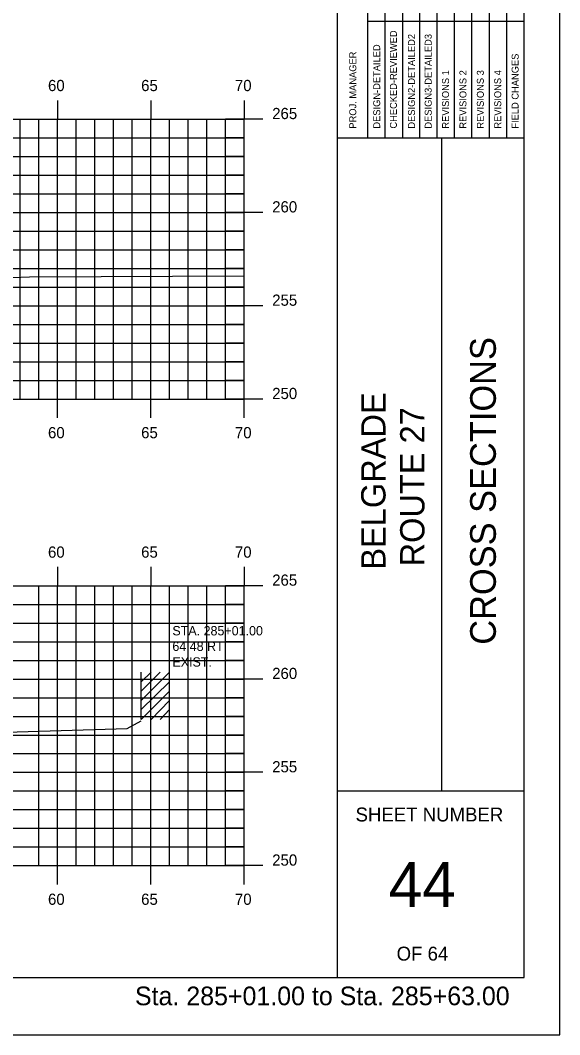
# Model space of a CAD drawing. Extents: x 856680 to 856850, y 366268 to 366378.
# Drawn here: x 856821.1 to 856850, y 366268.2 to 366322.5 of the extents above; entities that cross this region are included whole.
import ezdxf

# ---------------------------------------------------------------- set-up
doc = ezdxf.new("R2010")
doc.units = 0
for name, color, linetype in [('BORDER', 7, 'Continuous'), ('D_Text_Monospaced', 7, 'Continuous'), ('H_V ANNOTATION', 7, 'Continuous'), ('HIGHWAY_TITLE', 7, 'Continuous'), ('MAJOR', 7, 'Continuous'), ('MINOR', 7, 'Continuous'), ('PLOT BOUNDARY', 7, 'Continuous'), ('S_Buildings', 7, 'Continuous'), ('S_Roadway_Centerline', 7, 'Continuous')]:
    doc.layers.add(name, color=color, linetype=linetype)

msp = doc.modelspace()

# ---------------------------------------------------------------- linework, layer by layer
at = {"layer": 'BORDER'}
for p, q in [((856838.116, 366271.236), (856838.116, 366376.239)), ((856848.116, 366271.236), (856848.116, 366376.236)), ((856838.116, 366316.239), (856848.116, 366316.239)), ((856843.707, 366281.239), (856843.707, 366316.239)), ((856838.116, 366281.239), (856848.116, 366281.239)), ((856688.116, 366271.236), (856848.116, 366271.236))]:
    msp.add_line(p, q, dxfattribs=at)
for points in [[(856840.664, 366316.242), (856840.664, 366333.739)], [(856841.596, 366333.739), (856841.596, 366316.242)], [(856842.527, 366316.242), (856842.527, 366333.739)], [(856843.459, 366316.242), (856843.459, 366333.739)], [(856844.391, 366316.242), (856844.391, 366333.739)], [(856845.322, 366316.242), (856845.322, 366333.739)], [(856846.254, 366316.242), (856846.254, 366333.739)], [(856847.186, 366316.242), (856847.186, 366333.739)], [(856839.732, 366316.242), (856839.732, 366333.033)], [(856839.731, 366322.489), (856848.116, 366322.489)]]:
    msp.add_lwpolyline(points, dxfattribs=at)
at = {"layer": 'MAJOR'}
for p, q in [((856823.116, 366318.238), (856823.116, 366317.236)), ((856828.116, 366318.238), (856828.116, 366317.236)), ((856833.116, 366318.238), (856833.116, 366317.236)), ((856693.116, 366317.236), (856833.116, 366317.236)), ((856693.116, 366317.236), (856833.116, 366317.236)), ((856823.116, 366302.236), (856823.116, 366317.236)), ((856828.116, 366302.236), (856828.116, 366317.236)), ((856834.118, 366317.236), (856832.114, 366317.236)), ((856833.116, 366302.236), (856833.116, 366317.236)), ((856833.116, 366302.236), (856833.116, 366317.236)), ((856693.116, 366312.236), (856833.116, 366312.236)), ((856834.118, 366312.236), (856832.114, 366312.236)), ((856693.116, 366307.236), (856833.116, 366307.236)), ((856834.118, 366307.236), (856832.114, 366307.236)), ((856693.116, 366302.236), (856833.116, 366302.236)), ((856693.116, 366302.236), (856833.116, 366302.236)), ((856823.116, 366301.234), (856823.116, 366302.236)), ((856828.116, 366301.234), (856828.116, 366302.236)), ((856834.118, 366302.236), (856832.114, 366302.236)), ((856833.116, 366301.234), (856833.116, 366302.236)), ((856823.116, 366293.238), (856823.116, 366292.236)), ((856828.116, 366293.238), (856828.116, 366292.236)), ((856833.116, 366293.238), (856833.116, 366292.236)), ((856693.116, 366292.236), (856833.116, 366292.236)), ((856693.116, 366292.236), (856833.116, 366292.236)), ((856823.116, 366277.236), (856823.116, 366292.236)), ((856828.116, 366277.236), (856828.116, 366292.236)), ((856834.118, 366292.236), (856832.114, 366292.236)), ((856833.116, 366277.236), (856833.116, 366292.236)), ((856833.116, 366277.236), (856833.116, 366292.236)), ((856693.116, 366287.236), (856833.116, 366287.236)), ((856834.118, 366287.236), (856832.114, 366287.236)), ((856693.116, 366282.236), (856833.116, 366282.236)), ((856834.118, 366282.236), (856832.114, 366282.236)), ((856693.116, 366277.236), (856833.116, 366277.236)), ((856693.116, 366277.236), (856833.116, 366277.236)), ((856823.116, 366276.234), (856823.116, 366277.236)), ((856828.116, 366276.234), (856828.116, 366277.236)), ((856834.118, 366277.236), (856832.114, 366277.236)), ((856833.116, 366276.234), (856833.116, 366277.236))]:
    msp.add_line(p, q, dxfattribs=at)
at = {"layer": 'MINOR'}
for p, q in [((856821.116, 366302.236), (856821.116, 366317.236)), ((856822.116, 366302.236), (856822.116, 366317.236)), ((856824.116, 366302.236), (856824.116, 366317.236)), ((856825.116, 366302.236), (856825.116, 366317.236)), ((856826.116, 366302.236), (856826.116, 366317.236)), ((856827.116, 366302.236), (856827.116, 366317.236)), ((856829.116, 366302.236), (856829.116, 366317.236)), ((856830.116, 366302.236), (856830.116, 366317.236)), ((856831.116, 366302.236), (856831.116, 366317.236)), ((856832.116, 366302.236), (856832.116, 366317.236)), ((856693.116, 366316.236), (856833.116, 366316.236)), ((856833.116, 366316.236), (856832.114, 366316.236)), ((856693.116, 366315.236), (856833.116, 366315.236)), ((856833.116, 366315.236), (856832.114, 366315.236)), ((856693.116, 366314.236), (856833.116, 366314.236)), ((856833.116, 366314.236), (856832.114, 366314.236)), ((856693.116, 366313.236), (856833.116, 366313.236)), ((856833.116, 366313.236), (856832.114, 366313.236)), ((856693.116, 366311.236), (856833.116, 366311.236)), ((856833.116, 366311.236), (856832.114, 366311.236)), ((856693.116, 366310.236), (856833.116, 366310.236)), ((856833.116, 366310.236), (856832.114, 366310.236)), ((856693.116, 366309.236), (856833.116, 366309.236)), ((856833.116, 366309.236), (856832.114, 366309.236)), ((856693.116, 366308.236), (856833.116, 366308.236)), ((856833.116, 366308.236), (856832.114, 366308.236)), ((856693.116, 366306.236), (856833.116, 366306.236)), ((856833.116, 366306.236), (856832.114, 366306.236)), ((856693.116, 366305.236), (856833.116, 366305.236)), ((856833.116, 366305.236), (856832.114, 366305.236)), ((856693.116, 366304.236), (856833.116, 366304.236)), ((856833.116, 366304.236), (856832.114, 366304.236)), ((856693.116, 366303.236), (856833.116, 366303.236)), ((856833.116, 366303.236), (856832.114, 366303.236)), ((856822.116, 366277.236), (856822.116, 366292.236)), ((856824.116, 366277.236), (856824.116, 366292.236)), ((856825.116, 366277.236), (856825.116, 366292.236)), ((856826.116, 366277.236), (856826.116, 366292.236)), ((856827.116, 366277.236), (856827.116, 366292.236)), ((856829.116, 366277.236), (856829.116, 366292.236)), ((856830.116, 366277.236), (856830.116, 366292.236)), ((856831.116, 366277.236), (856831.116, 366292.236)), ((856832.116, 366277.236), (856832.116, 366292.236)), ((856693.116, 366291.236), (856833.116, 366291.236)), ((856833.116, 366291.236), (856832.114, 366291.236)), ((856693.116, 366290.236), (856833.116, 366290.236)), ((856833.116, 366290.236), (856832.114, 366290.236)), ((856693.116, 366289.236), (856833.116, 366289.236)), ((856833.116, 366289.236), (856832.114, 366289.236)), ((856693.116, 366288.236), (856833.116, 366288.236)), ((856833.116, 366288.236), (856832.114, 366288.236)), ((856693.116, 366286.236), (856833.116, 366286.236)), ((856833.116, 366286.236), (856832.114, 366286.236)), ((856693.116, 366285.236), (856833.116, 366285.236)), ((856833.116, 366285.236), (856832.114, 366285.236)), ((856693.116, 366284.236), (856833.116, 366284.236)), ((856833.116, 366284.236), (856832.114, 366284.236)), ((856693.116, 366283.236), (856833.116, 366283.236)), ((856833.116, 366283.236), (856832.114, 366283.236)), ((856693.116, 366281.236), (856833.116, 366281.236)), ((856833.116, 366281.236), (856832.114, 366281.236)), ((856693.116, 366280.236), (856833.116, 366280.236)), ((856833.116, 366280.236), (856832.114, 366280.236)), ((856693.116, 366279.236), (856833.116, 366279.236)), ((856833.116, 366279.236), (856832.114, 366279.236)), ((856693.116, 366278.236), (856833.116, 366278.236)), ((856833.116, 366278.236), (856832.114, 366278.236))]:
    msp.add_line(p, q, dxfattribs=at)
at = {"layer": 'PLOT BOUNDARY'}
msp.add_lwpolyline([(856680.023, 366268.177), (856850.023, 366268.177), (856850.023, 366378.177), (856680.023, 366378.177)], close=True, dxfattribs=at)
at = {"layer": 'S_Buildings'}
for p, q in [((856827.6, 366285.074), (856827.6, 366287.6)), ((856827.6, 366286.091), (856829.109, 366287.6)), ((856827.6, 366286.583), (856828.617, 366287.6)), ((856827.6, 366287.076), (856828.125, 366287.6)), ((856827.6, 366285.599), (856829.109, 366287.076)), ((856827.6, 366285.074), (856829.109, 366286.583)), ((856828.125, 366285.074), (856829.109, 366286.091)), ((856828.617, 366285.074), (856829.109, 366285.599))]:
    msp.add_line(p, q, dxfattribs=at)
at = {"layer": 'S_Roadway_Centerline'}
for points in [[(856788.463, 366309.06), (856804.446, 366308.878), (856806.319, 366308.852), (856807.253, 366308.849), (856807.696, 366308.849), (856808.101, 366308.85), (856808.281, 366308.851), (856808.489, 366308.853), (856819.433, 366308.709), (856819.506, 366308.709), (856819.606, 366308.709), (856819.725, 366308.708), (856819.769, 366308.707), (856821.607, 366308.779), (856833.116, 366308.838)], [(856791.541, 366284.755), (856792.375, 366284.743), (856793.483, 366284.724), (856813.618, 366284.43), (856815.099, 366284.402), (856815.786, 366284.389), (856816.868, 366284.367), (856817.354, 366284.358), (856818.009, 366284.346), (856818.571, 366284.337), (856826.84, 366284.577), (856827.6, 366284.998)]]:
    msp.add_lwpolyline(points, dxfattribs=at)

# ---------------------------------------------------------------- texts
at = {"layer": 'BORDER'}
for s, height, rotation, p in [('CHECKED-REVIEWED', 0.37275, 90, (856841.297, 366316.727)), ('DESIGN2-DETAILED2', 0.37275, 90, (856842.266, 366316.727)), ('DESIGN3-DETAILED3', 0.37275, 90, (856843.161, 366316.727)), ('DESIGN-DETAILED', 0.37275, 90, (856840.403, 366316.727)), ('PROJ. MANAGER', 0.37275, 90, (856839.121, 366316.727)), ('FIELD CHANGES', 0.37275, 90, (856847.819, 366316.727)), ('REVISIONS 1', 0.37275, 90, (856844.092, 366316.727)), ('REVISIONS 2', 0.37275, 90, (856845.024, 366316.727)), ('REVISIONS 3', 0.37275, 90, (856845.956, 366316.727)), ('REVISIONS 4', 0.37275, 90, (856846.888, 366316.727)), ('CROSS SECTIONS', 1.37787, 90, (856846.601, 366289.073)), ('SHEET NUMBER', 0.74527, 360, (856839.082, 366279.603)), ('44', 2.4194, 360, (856840.863, 366275.019)), ('OF 64', 0.7453, 360, (856841.283, 366272.149))]:
    msp.add_text(s, height=height, rotation=rotation, dxfattribs=at).set_placement(p)
at = {"layer": 'D_Text_Monospaced'}
for s, height, p in [('STA. 285+01.00', 0.49998, (856829.267, 366289.573)), ('64.48 RT.', 0.5, (856829.267, 366288.739)), ('EXIST. ', 0.5, (856829.267, 366287.899))]:
    msp.add_text(s, height=height, dxfattribs=at).set_placement(p)
at = {"layer": 'H_V ANNOTATION'}
for s, height, p in [('60', 0.6, (856822.602, 366318.736)), ('65', 0.6, (856827.594, 366318.736)), ('70', 0.6, (856832.618, 366318.736)), ('265', 0.6, (856834.616, 366317.236)), ('260', 0.6, (856834.616, 366312.236)), ('255', 0.6, (856834.616, 366307.236)), ('250', 0.6, (856834.616, 366302.236)), ('60', 0.6, (856822.602, 366300.136)), ('65', 0.6, (856827.594, 366300.136)), ('70', 0.6, (856832.618, 366300.136)), ('60', 0.6, (856822.602, 366293.736)), ('65', 0.6, (856827.594, 366293.736)), ('70', 0.6, (856832.618, 366293.736)), ('265', 0.6, (856834.616, 366292.236)), ('260', 0.6, (856834.616, 366287.236)), ('255', 0.6, (856834.616, 366282.236)), ('250', 0.6, (856834.616, 366277.236)), ('60', 0.6, (856822.602, 366275.136)), ('65', 0.6, (856827.594, 366275.136)), ('70', 0.6, (856832.618, 366275.136)), ('Sta. 285+01.00 to Sta. 285+63.00', 1.0002, (856827.262, 366269.756))]:
    msp.add_text(s, height=height, dxfattribs=at).set_placement(p)
at = {"layer": 'HIGHWAY_TITLE'}
for s, p in [('BELGRADE', (856840.689, 366293.095)), ('ROUTE 27', (856842.776, 366293.269))]:
    msp.add_text(s, height=1.3043, rotation=90, dxfattribs=at).set_placement(p)

doc.saveas('drawing.dxf')
